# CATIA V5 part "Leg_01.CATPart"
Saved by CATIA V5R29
Part number: Leg_01
Source: Unknown
Bounding box of the stored display mesh (mm): x -40 to 40, y -50 to 50, z 0 to 600
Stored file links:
  C:\가치같이\SmartFactory_BoxErectorConveyor\Boxing(over)\Taping(over)\Leg_01.CATPart
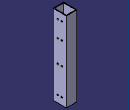
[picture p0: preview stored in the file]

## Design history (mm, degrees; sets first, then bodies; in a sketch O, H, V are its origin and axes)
Body1 (main body)
  Solid1 "PartBody": solid without history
